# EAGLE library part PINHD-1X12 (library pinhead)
PIN HEADER
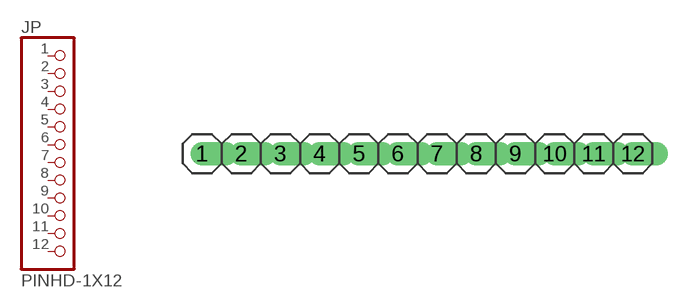
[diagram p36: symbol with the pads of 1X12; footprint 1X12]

Designator prefix JP

## PINHD-1X12  [1X12]
1  1  pas
2  2  pas
3  3  pas
4  4  pas
5  5  pas
6  6  pas
7  7  pas
8  8  pas
9  9  pas
10  10  pas
11  11  pas
12  12  pas

## Footprint 1X12 (pad centres in mm)
PIN HEADER
drill 1.016 offset: 1 -13.97,0; 2 -11.43,0; 3 -8.89,0; 4 -6.35,0; 5 -3.81,0; 6 -1.27,0; 7 1.27,0; 8 3.81,0; 9 6.35,0; 10 8.89,0; 11 11.43,0; 12 13.97,0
